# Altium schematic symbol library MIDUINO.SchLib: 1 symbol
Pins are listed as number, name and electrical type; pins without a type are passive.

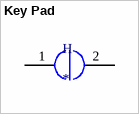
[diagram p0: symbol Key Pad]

## Key Pad
designator H
pins: 1, 2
